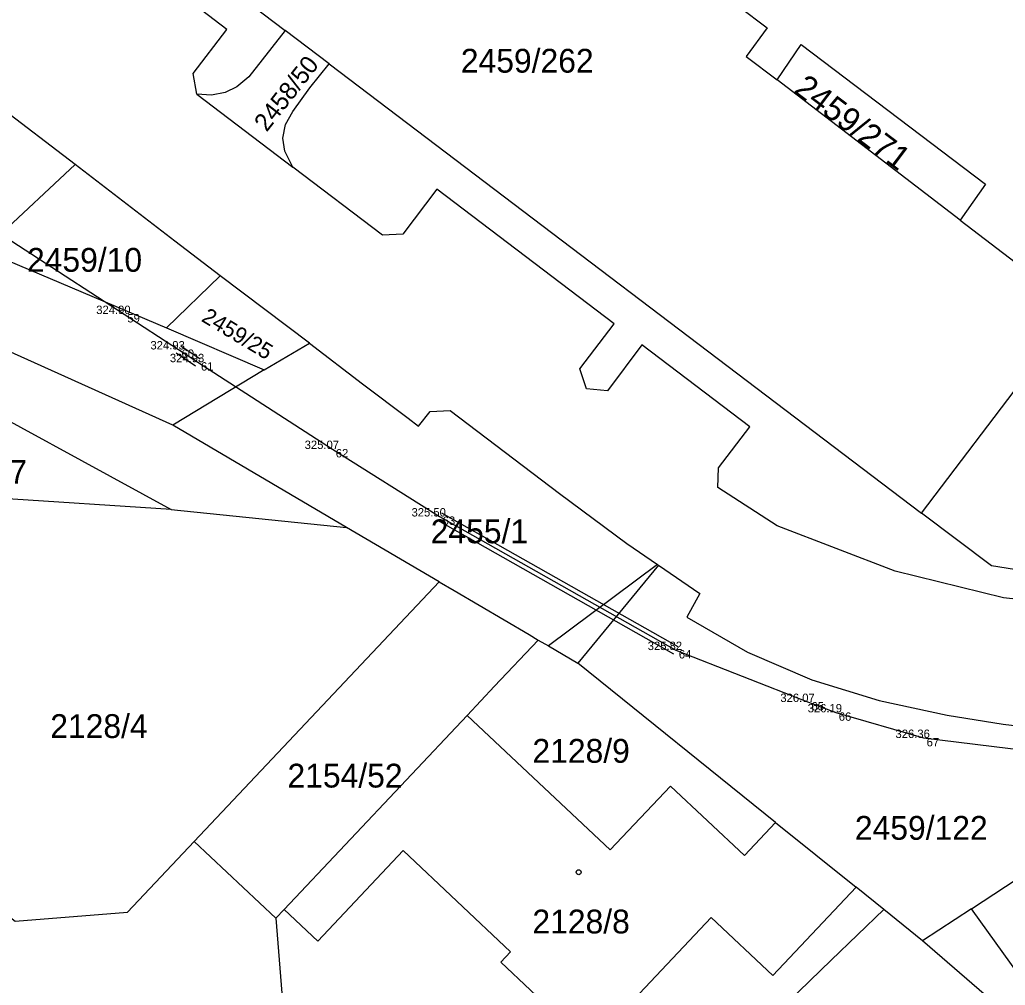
# Model space of a CAD drawing. Extents: x -606208 to -605570, y -1157873 to -1157573.
# Drawn here: x -605930.7 to -605860.4, y -1157769.8 to -1157700.9 of the extents above; entities that cross this region are included whole.
import ezdxf

# ---------------------------------------------------------------- set-up
doc = ezdxf.new("R2010")
doc.units = 0
for name, color, linetype in [('Vrstva 30', 7, 'Continuous'), ('Vrstva 38', 7, 'Continuous'), ('Vrstva 58', 7, 'Continuous'), ('Vrstva 59', 7, 'Continuous'), ('Vrstva 60', 7, 'Continuous'), ('Vrstva 62', 7, 'Continuous')]:
    doc.layers.add(name, color=color, linetype=linetype)

msp = doc.modelspace()

# ---------------------------------------------------------------- linework, layer by layer
at = {"layer": 'Vrstva 30'}
msp.add_lwpolyline([(-605936.47, -1157713.34), (-605923.26, -1157721.89), (-605919.39, -1157724.42), (-605918, -1157725.33), (-605908.38, -1157731.53), (-605900.75, -1157736.35), (-605883.89, -1157745.89), (-605874.42, -1157749.6), (-605872.47, -1157750.34), (-605866.2, -1157752.17), (-605853.97, -1157753.65)], dxfattribs=at)
at = {"layer": 'Vrstva 38'}
for p, q in [((-605919.23, -1157724.17), (-605917.84, -1157725.08)), ((-605919.55, -1157724.67), (-605918.16, -1157725.58)), ((-605900.6, -1157736.09), (-605883.74, -1157745.63)), ((-605900.9, -1157736.61), (-605884.04, -1157746.15))]:
    msp.add_line(p, q, dxfattribs=at)
at = {"layer": 'Vrstva 60'}
for p, q in [((-605923.26, -1157721.89), (-605923.26, -1157721.89)), ((-605919.39, -1157724.42), (-605919.39, -1157724.42)), ((-605918, -1157725.33), (-605918, -1157725.33)), ((-605908.38, -1157731.53), (-605908.38, -1157731.53)), ((-605900.75, -1157736.35), (-605900.75, -1157736.35)), ((-605883.89, -1157745.89), (-605883.89, -1157745.89)), ((-605874.42, -1157749.6), (-605874.42, -1157749.6)), ((-605872.47, -1157750.34), (-605872.47, -1157750.34)), ((-605866.2, -1157752.17), (-605866.2, -1157752.17))]:
    msp.add_line(p, q, dxfattribs=at)
at = {"layer": 'Vrstva 62'}
for p, q in [((-605908.62, -1157704.02), (-605911.76, -1157701.63)), ((-605908.62, -1157704.02), (-605866.35, -1157736.11)), ((-605863.59, -1157715.18), (-605876.65, -1157705.17)), ((-605926.77, -1157711.22), (-605933.66, -1157705.95)), ((-605918.08, -1157706.18), (-605911.22, -1157711.39)), ((-605926.77, -1157711.22), (-605933.32, -1157717.34)), ((-605863.59, -1157715.18), (-605855.29, -1157721.53)), ((-605933.32, -1157717.34), (-605920.23, -1157722.87)), ((-605920.23, -1157722.87), (-605916.4, -1157719.15)), ((-605910.04, -1157723.98), (-605916.4, -1157719.15)), ((-605919.8, -1157729.83), (-605938.64, -1157721.34)), ((-605919.8, -1157729.83), (-605938.64, -1157721.34)), ((-605866.35, -1157736.11), (-605855.29, -1157721.53)), ((-605920.23, -1157722.87), (-605913.26, -1157725.87)), ((-605913.26, -1157725.87), (-605910.04, -1157723.98)), ((-605913.26, -1157725.87), (-605919.8, -1157729.83)), ((-605907.38, -1157737.13), (-605919.8, -1157729.83)), ((-605907.38, -1157737.13), (-605919.8, -1157729.83)), ((-605919.91, -1157735.84), (-605939.73, -1157734.56)), ((-605919.91, -1157735.84), (-605907.38, -1157737.13)), ((-605900.77, -1157741.02), (-605907.38, -1157737.13)), ((-605900.77, -1157741.02), (-605907.38, -1157737.13)), ((-605885.2, -1157739.77), (-605892.96, -1157745.6)), ((-605885.13, -1157739.82), (-605890.88, -1157746.83)), ((-605918.26, -1157759.56), (-605900.77, -1157741.02)), ((-605876.76, -1157758.2), (-605890.88, -1157746.83)), ((-605876.76, -1157758.2), (-605890.88, -1157746.83)), ((-605911.85, -1157764.43), (-605898.78, -1157750.56)), ((-605862.77, -1157764.37), (-605843.78, -1157751.83)), ((-605876.76, -1157758.2), (-605871.01, -1157762.83)), ((-605876.76, -1157758.2), (-605871.01, -1157762.83)), ((-605912.44, -1157765.05), (-605918.26, -1157759.56)), ((-605869.03, -1157764.42), (-605871.01, -1157762.83)), ((-605869.03, -1157764.42), (-605871.01, -1157762.83)), ((-605911.85, -1157764.43), (-605912.44, -1157765.05)), ((-605866.26, -1157766.65), (-605869.03, -1157764.42)), ((-605866.26, -1157766.65), (-605869.03, -1157764.42)), ((-605862.77, -1157764.37), (-605866.26, -1157766.65))]:
    msp.add_line(p, q, dxfattribs=at)
for points in [[(-605923.7, -1157692.57), (-605923.46, -1157692.75), (-605911.76, -1157701.63)], [(-605918.08, -1157706.18), (-605918.33, -1157704.72), (-605915.93, -1157701.57), (-605923.57, -1157695.72), (-605926.03, -1157698.76), (-605927.39, -1157699.1)], [(-605881.41, -1157698.37), (-605877.36, -1157701.44), (-605878.85, -1157703.49), (-605876.65, -1157705.17)], [(-605911.76, -1157701.63), (-605914.37, -1157704.94), (-605915.22, -1157705.66), (-605916.06, -1157706.06), (-605917.03, -1157706.25), (-605918.08, -1157706.18)], [(-605876.65, -1157705.17), (-605874.93, -1157702.63), (-605861.78, -1157712.61), (-605863.59, -1157715.18)], [(-605911.22, -1157711.39), (-605911.79, -1157710.26), (-605911.93, -1157709.33), (-605911.74, -1157708.35), (-605911.22, -1157707.43), (-605910.01, -1157705.74), (-605908.62, -1157704.02)], [(-605916.4, -1157719.15), (-605919.64, -1157716.69), (-605926.77, -1157711.22)], [(-605852.36, -1157743.04), (-605860.5, -1157742.15), (-605868.22, -1157740.25), (-605876.64, -1157737.01), (-605880.88, -1157734.29), (-605880.83, -1157732.87), (-605878.59, -1157729.95), (-605886.32, -1157724.09), (-605888.76, -1157727.37), (-605890.27, -1157727.23), (-605890.73, -1157725.81), (-605888.28, -1157722.6), (-605900.95, -1157712.97), (-605903.38, -1157716.18), (-605904.82, -1157716.25), (-605911.22, -1157711.39)], [(-605837.22, -1157721.71), (-605835.42, -1157722.92), (-605848.53, -1157740.31), (-605849.14, -1157740.82), (-605849.91, -1157741), (-605857.93, -1157740.41), (-605861.35, -1157739.87), (-605866.35, -1157736.11)], [(-605910.04, -1157723.98), (-605906.24, -1157726.87), (-605903, -1157729.33), (-605902.25, -1157729.9), (-605901.42, -1157728.85), (-605899.98, -1157728.77), (-605892.19, -1157734.7), (-605887.38, -1157738.27), (-605885.2, -1157739.77), (-605885.13, -1157739.82)], [(-605938.99, -1157725.54), (-605937.1, -1157726.48), (-605919.91, -1157735.84)], [(-605885.13, -1157739.82), (-605882.17, -1157741.85), (-605883.1, -1157743.55), (-605878.76, -1157746.03), (-605874.17, -1157748.02), (-605869.37, -1157749.5), (-605864.5, -1157750.55), (-605860.51, -1157751.19), (-605855.56, -1157751.77), (-605850.57, -1157752.02), (-605845.2, -1157751.97), (-605843.78, -1157751.83)], [(-605900.77, -1157741.02), (-605899.7, -1157741.64), (-605894.36, -1157744.78), (-605893.7, -1157745.18)], [(-605900.77, -1157741.02), (-605899.7, -1157741.64), (-605894.36, -1157744.78), (-605893.7, -1157745.18)], [(-605893.7, -1157745.18), (-605896.82, -1157748.48), (-605898.78, -1157750.56)], [(-605893.7, -1157745.18), (-605892.96, -1157745.6), (-605890.88, -1157746.83)], [(-605893.7, -1157745.18), (-605892.96, -1157745.6), (-605890.88, -1157746.83)], [(-605898.78, -1157750.56), (-605888.56, -1157760.17), (-605884.26, -1157755.61), (-605878.98, -1157760.56), (-605876.76, -1157758.2)], [(-605941.6, -1157757.14), (-605931.04, -1157765.25), (-605923.02, -1157764.61), (-605918.26, -1157759.56)], [(-605836.75, -1157759.27), (-605857.17, -1157772.16), (-605862.77, -1157764.37)], [(-605871.01, -1157762.83), (-605876.95, -1157769.13), (-605881.35, -1157764.98), (-605890.03, -1157774.17), (-605896.37, -1157768.19), (-605895.68, -1157767.44), (-605903.34, -1157760.21), (-605909.43, -1157766.68), (-605911.85, -1157764.43)], [(-605869.03, -1157764.42), (-605872.78, -1157768.05), (-605895.1, -1157789.66)], [(-605912.44, -1157765.05), (-605911.72, -1157773.97), (-605895.1, -1157789.66)], [(-605850.18, -1157780.56), (-605858.17, -1157773.65), (-605866.26, -1157766.65)], [(-605850.18, -1157780.56), (-605858.17, -1157773.65), (-605866.26, -1157766.65)]]:
    msp.add_lwpolyline(points, dxfattribs=at)
msp.add_circle((-605890.817, -1157761.759), 0.175, dxfattribs=at)

# ---------------------------------------------------------------- texts
at = {"layer": 'Vrstva 30'}
msp.add_text('DÉLKA OPTOTRASY 710m', height=8, rotation=326.99002, dxfattribs=at).set_placement((-606030.83, -1157728.28))
at = {"layer": 'Vrstva 58'}
for s, p in [('324.90 ', (-605925.26, -1157721.89)), ('324.93 ', (-605921.39, -1157724.42)), ('324.93 ', (-605920, -1157725.33)), ('325.07 ', (-605910.38, -1157731.53)), ('325.50 ', (-605902.75, -1157736.35)), ('325.82 ', (-605885.89, -1157745.89)), ('326.07 ', (-605876.42, -1157749.6)), ('326.19 ', (-605874.47, -1157750.34)), ('326.36 ', (-605868.2, -1157752.17))]:
    msp.add_text(s, height=0.6, dxfattribs=at).set_placement(p)
at = {"layer": 'Vrstva 59'}
for s, p in [(' 59', (-605923.26, -1157722.49)), (' 60', (-605919.39, -1157725.02)), (' 61', (-605918, -1157725.93)), (' 62', (-605908.38, -1157732.13)), (' 63', (-605900.75, -1157736.95)), (' 64', (-605883.89, -1157746.49)), (' 65', (-605874.42, -1157750.2)), (' 66', (-605872.47, -1157750.94)), (' 67', (-605866.2, -1157752.77))]:
    msp.add_text(s, height=0.6, dxfattribs=at).set_placement(p)
at = {"layer": 'Vrstva 62'}
for s, p in [('2459/262', (-605899.23, -1157704.65)), ('2459/10', (-605930.2, -1157718.87)), ('2128/7', (-605937.15, -1157734.01)), ('2455/1', (-605901.38, -1157738.26)), ('2128/4', (-605928.54, -1157752.17)), ('2128/9', (-605894.118, -1157753.94)), ('2154/52', (-605911.605, -1157755.71)), ('2459/122', (-605871.1, -1157759.44)), ('2128/8', (-605894.119, -1157766.13))]:
    msp.add_text(s, height=1.7, dxfattribs=at).set_placement(p)
for s, height, rotation, p in [('2458/50', 1.271, 52, (-605913.087, -1157708.935)), ('2459/271', 1.7, 323, (-605875.548, -1157706.016)), ('2459/25', 1.139, 329, (-605917.82, -1157722.36))]:
    msp.add_text(s, height=height, rotation=rotation, dxfattribs=at).set_placement(p)

doc.saveas('drawing.dxf')
